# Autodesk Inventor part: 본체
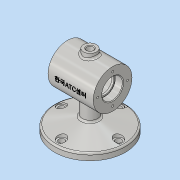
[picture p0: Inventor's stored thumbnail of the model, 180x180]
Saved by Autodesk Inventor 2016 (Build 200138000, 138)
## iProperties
Created: 2018-12
Part Number: 본체
Material: 알루미늄 6061
Document SubType Name: Modeling
Designer: Administrator
Density: 2.7 g/cm^3
Appearance: 알루미늄 - 평지
Mass: 659.77 g
Surface Area: 551.11 cm^2
Volume: 244.359 cm^3
Author: Administrator
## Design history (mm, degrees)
sketch "스케치1"
  geometry: C1 r 55 at (0, 0); 1 further point
  constraints: 1 centre point, 1 coincident
  dimensions: "d0" = 110 diameter of C1
extrude "돌출1" new body sketch "스케치1" distance "d1" = 10; taper "d2" = 0 deg
sketch "스케치2"
  geometry: L1 (75, 35)-(75, -35); L2 (0, 55)-(0, -55) reference; L3 (75, 35)-(105, 35); L4 (105, 35)-(105, -35); L5 (105, -35)-(75, -35); 3 further points
  constraints: 8 end point, 2 midpoint, 2 perpendicular, 1 horizontal, 1 horizontal alignment, 1 vertical
  dimensions: "d3" = 75 distance between parallel lines of L2 L1; "d4" = 70 distance of L1.start L1.end; "d5" = 60 diameter of L4 L1
revolve "회전1" sketch "스케치2" stored, may be unused: angle "d6" = 90 deg
node "작업 평면1"
sketch "스케치3"
  geometry: C1 r 10 at (0, 0); 1 further point
  constraints: 1 centre point, 1 coincident
  dimensions: "d8" = 20 diameter of C1
extrude "돌출2" join sketch "스케치3" distance "d9" = 112; taper "d10" = 0 deg
sketch "스케치4"
  geometry: L1 (0, -55)-(10, -55) reference; L2 (10, -55)-(22.058, -10); L3 (45, -10)-(10, -10) reference; L4 (112, 10)-(112, -10) reference; L5 (0, 55)-(0, -55) reference; L6 (112, 0)-(0, 0); L7 (10, -55)-(10, 55) reference; L8 (10, -55)-(10, 0); L9 (22.058, -10)-(22.058, 0)
  constraints: 8 end point, 2 midpoint, 2 point on line, 1 horizontal, 1 perpendicular
  dimensions: "d11" = 75 deg angle of L2 L1
revolve "회전2" sketch "스케치4" stored, may be unused: angle "d13" = 90 deg
sketch "스케치9"
  geometry: C1 r 12 at (0, 0); 1 further point
  constraints: 1 centre point, 1 coincident
  dimensions: "d29" = 24 diameter of C1
extrude "돌출3" join sketch "스케치9" distance "d30" = 75; taper "d31" = 0 deg
sketch "스케치6"
  geometry: L1 (112, 10)-(112, -10) reference; L2 (0, 0)-(0, -55) reference; L3 (0, 0)-(0, -55) reference; L4 (105, 35)-(105, -35) reference; 2 further points
  constraints: 1 horizontal alignment, 1 midpoint, 1 other
  dimensions: "d78" = 30 distance from line of point (75, 0) L4
feature "엠보싱1" sketch "스케치6" dims "d1" = 10, "d2" = 0, "d15" = 0.5, "d16" = 0
sketch "스케치8"
  geometry: L1 (45, 35)-(105, 35) reference; L2 (45, -35)-(105, -35) reference; L3 (75, 35)-(75, -35); L4 (75, 35)-(91, 35); L5 (91, 35)-(91, 23); L6 (91, 23)-(89, 23); L7 (89, 23)-(89, 20); L8 (89, 20)-(97, 20); L9 (100, 17)-(100, -17); L10 (97, -20)-(89, -20); L11 (89, -20)-(89, -23); L12 (89, -23)-(91, -23); L13 (91, -23)-(91, -35); L14 (91, -35)-(75, -35); A1 r 3 centre (97, 17) between (100, 17) and (97, 20); A2 r 3 centre (97, -17) between (97, -20) and (100, -17); 3 further points
  constraints: 24 end point, 8 point on line, 6 perpendicular, 4 point on circle, 4 tangent, 3 collinear, 2 centre point, 2 midpoint, 2 vertical, 1 equal radius
  dimensions: "d17" = 50 diameter of L9 L3; "d18" = 32 diameter of L5 L3; "d20" = 32 diameter of L13 L3; "d21" = 28 diameter of L7 L3; "d22" = 12 distance of L4.end L5.end; "d23" = 40 distance of point (100, 20) point (100, -20); "d25" = 3 radius of A1
revolve "회전3" sketch "스케치8" stored, may be unused: angle "d24" = 90 deg
chamfer "모따기1" distance "d26" = 1; stored, may be unused: second distance "d27" = 2, angle "d28" = 45 deg
sketch "스케치11" dims "d33" = 88
  geometry: 3 further points
  constraints: 2 horizontal alignment, 1 coincident, 2 other
hole "구멍1" sketch "스케치11" at (44, 0) diameter "d34" = 9; stored, may be unused: countersink angle "d38" = 90 deg, drill point angle "d40" = 0 deg; dims "d35" = 6, "d36" = 4, "d37" = 2, "d39" = 10
hole "구멍2" diameter "d43" = 14; stored, may be unused: countersink angle "d47" = 90 deg, drill point angle "d49" = 0 deg; dims "d41" = 10, "d42" = 10, "d44" = 6, "d45" = 4, "d46" = 2, "d48" = 10
sketch "스케치12"
  geometry: C1 r 30 at (0, 0) reference; 2 further points
  constraints: 1 vertical alignment
  dimensions: "d53" = 23 distance of C1.centre point (0, 23)
hole "구멍3" sketch "스케치12" at (0, 23) diameter "d54" = 3.242; stored, may be unused: countersink angle "d58" = 90 deg, drill point angle "d60" = 118 deg; dims "d55" = 8, "d56" = 4, "d57" = 2, "d59" = 10
fillet "모깎기1" dims "d64" = 0.3
hole "구멍4" diameter "d67" = 10; stored, may be unused: countersink angle "d71" = 90 deg, drill point angle "d73" = 118 deg; dims "d68" = 8, "d69" = 4, "d70" = 2, "d72" = 20, "d79" = 10, "d80" = 10
chamfer "모따기2" distance "d74" = 1; stored, may be unused: second distance "d75" = 2, angle "d76" = 45 deg
fillet "모깎기2" dims "d77" = 3
node "솔리드1"
pattern_circular "원형 패턴1" dims angle "d51" = 360 deg
pattern_circular "원형 패턴2" dims angle "d62" = 360 deg
mirror "대칭2"
other parameters: "d7" = 112
